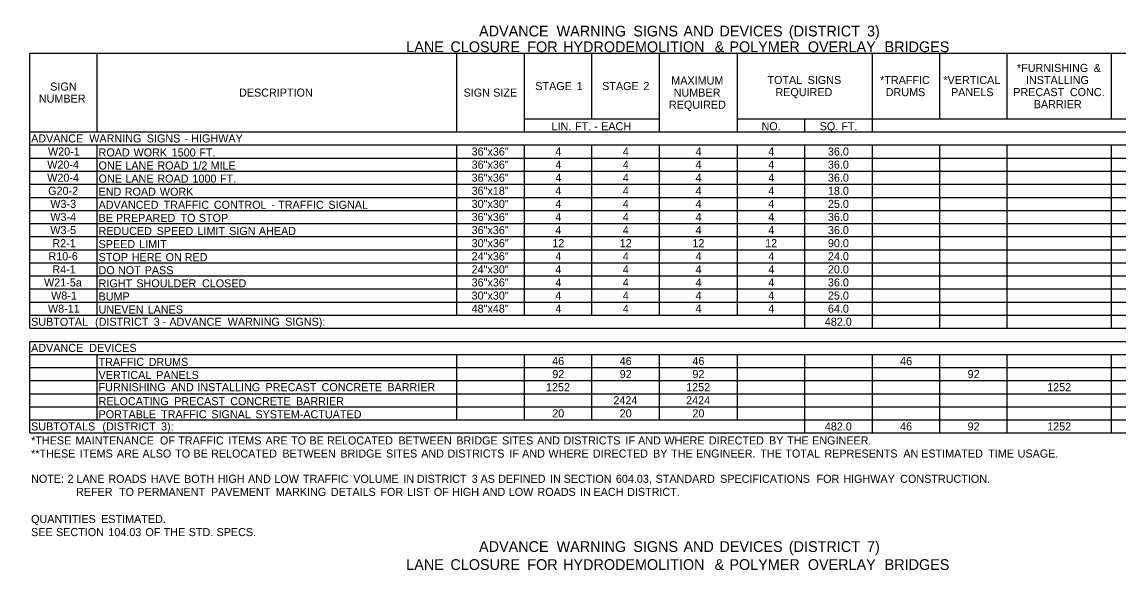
# Model space of a CAD drawing. Extents: x 544478 to 1930787, y -1948294 to 596640.
# Drawn here: x 544478 to 545294, y -1946531 to -1946122 of the extents above; entities that cross this region are included whole.
import ezdxf

# ---------------------------------------------------------------- set-up
doc = ezdxf.new("R2010")
doc.units = 0
doc.layers.add('Default', color=7, linetype='Continuous')

msp = doc.modelspace()

# ---------------------------------------------------------------- linework, layer by layer
at = {"layer": 'Default'}
for p, q in [((544478.43, -1946122.37), (544478.43, -1946122.37)), ((544484.28, -1946145.77), (545456.84, -1946145.77)), ((544484.28, -1946350.52), (544484.28, -1946145.77)), ((544484.28, -1946350.52), (544484.28, -1946145.77)), ((544534.49, -1946204.27), (544534.49, -1946145.77)), ((544802.13, -1946204.27), (544802.13, -1946145.77)), ((544852.34, -1946204.27), (544852.34, -1946145.77)), ((544902.55, -1946194.52), (544902.55, -1946145.77)), ((544952.76, -1946204.27), (544952.76, -1946145.77)), ((545010.78, -1946204.27), (545010.78, -1946145.77)), ((545111.2, -1946204.27), (545111.2, -1946145.77)), ((545161.41, -1946194.52), (545161.41, -1946145.77)), ((545211.63, -1946194.52), (545211.63, -1946145.77)), ((545289.14, -1946194.52), (545289.14, -1946145.77)), ((544852.34, -1946194.52), (544952.76, -1946194.52)), ((544952.76, -1946204.27), (544952.76, -1946194.52)), ((545010.78, -1946194.52), (545456.84, -1946194.52)), ((545060.99, -1946204.27), (545060.99, -1946194.52)), ((545111.2, -1946204.27), (545111.2, -1946194.52)), ((544484.28, -1946204.27), (545456.84, -1946204.27)), ((544952.76, -1946204.27), (545456.84, -1946204.27)), ((544484.28, -1946214.02), (545456.84, -1946214.02)), ((544534.49, -1946340.77), (544534.49, -1946214.02)), ((544534.49, -1946340.77), (544534.49, -1946214.02)), ((544802.13, -1946340.77), (544802.13, -1946214.02)), ((544802.13, -1946340.77), (544802.13, -1946214.02)), ((544852.34, -1946340.77), (544852.34, -1946214.02)), ((544852.34, -1946340.77), (544852.34, -1946214.02)), ((544902.55, -1946292.02), (544902.55, -1946214.02)), ((544902.55, -1946340.77), (544902.55, -1946214.02)), ((544952.76, -1946340.77), (544952.76, -1946214.02)), ((544952.76, -1946340.77), (544952.76, -1946214.02)), ((545010.78, -1946340.77), (545010.78, -1946214.02)), ((545060.99, -1946340.77), (545060.99, -1946214.02)), ((545060.99, -1946350.52), (545060.99, -1946214.02)), ((545111.2, -1946350.52), (545111.2, -1946214.02)), ((545111.2, -1946350.52), (545111.2, -1946214.02)), ((545161.41, -1946350.52), (545161.41, -1946214.02)), ((545161.41, -1946350.52), (545161.41, -1946214.02)), ((545211.63, -1946350.52), (545211.63, -1946214.02)), ((545211.63, -1946350.52), (545211.63, -1946214.02)), ((545289.14, -1946350.52), (545289.14, -1946214.02)), ((545289.14, -1946350.52), (545289.14, -1946214.02)), ((544484.28, -1946223.77), (545456.84, -1946223.77)), ((544484.28, -1946233.52), (545456.84, -1946233.52)), ((544484.28, -1946243.27), (545456.84, -1946243.27)), ((544484.28, -1946253.02), (545456.84, -1946253.02)), ((544484.28, -1946262.77), (545456.84, -1946262.77)), ((544484.28, -1946272.52), (545456.84, -1946272.52)), ((544484.28, -1946282.27), (545456.84, -1946282.27)), ((544484.28, -1946292.02), (545456.84, -1946292.02)), ((544484.28, -1946301.77), (545456.84, -1946301.77)), ((544902.55, -1946340.77), (544902.55, -1946301.77)), ((544484.28, -1946311.52), (545456.84, -1946311.52)), ((544484.28, -1946321.27), (545456.84, -1946321.27)), ((544484.28, -1946331.02), (545456.84, -1946331.02)), ((544484.28, -1946340.77), (545456.84, -1946340.77)), ((544484.28, -1946340.77), (545060.99, -1946340.77)), ((544484.28, -1946350.52), (545456.84, -1946350.52)), ((544484.28, -1946360.27), (545456.84, -1946360.27)), ((544484.28, -1946428.52), (544484.28, -1946360.27)), ((544484.28, -1946428.52), (544484.28, -1946360.27)), ((544534.49, -1946360.27), (545456.84, -1946360.27)), ((544484.28, -1946370.02), (545456.84, -1946370.02)), ((544534.49, -1946389.52), (544534.49, -1946370.02)), ((544534.49, -1946418.77), (544534.49, -1946370.02)), ((544802.13, -1946418.77), (544802.13, -1946370.02)), ((544802.13, -1946418.77), (544802.13, -1946370.02)), ((544852.34, -1946418.77), (544852.34, -1946370.02)), ((544852.34, -1946418.77), (544852.34, -1946370.02)), ((544902.55, -1946418.77), (544902.55, -1946370.02)), ((544902.55, -1946418.77), (544902.55, -1946370.02)), ((544952.76, -1946418.77), (544952.76, -1946370.02)), ((544952.76, -1946418.77), (544952.76, -1946370.02)), ((545010.78, -1946418.77), (545010.78, -1946370.02)), ((545060.99, -1946418.77), (545060.99, -1946370.02)), ((545060.99, -1946428.52), (545060.99, -1946370.02)), ((545111.2, -1946428.52), (545111.2, -1946370.02)), ((545111.2, -1946428.52), (545111.2, -1946370.02)), ((545161.41, -1946370.02), (545211.63, -1946370.02)), ((545161.41, -1946428.52), (545161.41, -1946370.02)), ((545161.41, -1946428.52), (545161.41, -1946370.02)), ((545211.63, -1946428.52), (545211.63, -1946370.02)), ((545289.14, -1946428.52), (545289.14, -1946370.02)), ((545289.14, -1946428.52), (545289.14, -1946370.02)), ((544484.28, -1946379.77), (545456.84, -1946379.77)), ((545211.63, -1946428.52), (545211.63, -1946379.77)), ((544484.28, -1946389.52), (545456.84, -1946389.52)), ((544484.28, -1946399.27), (544534.49, -1946399.27)), ((544484.28, -1946399.27), (544952.76, -1946399.27)), ((544534.49, -1946418.77), (544534.49, -1946399.27)), ((544802.13, -1946399.27), (544952.76, -1946399.27)), ((544952.76, -1946399.27), (545289.14, -1946399.27)), ((545010.78, -1946399.27), (545211.63, -1946399.27)), ((545211.63, -1946399.27), (545456.84, -1946399.27)), ((544484.28, -1946409.02), (545456.84, -1946409.02)), ((544484.28, -1946418.77), (545456.84, -1946418.77)), ((544484.28, -1946428.52), (545456.84, -1946428.52))]:
    msp.add_line(p, q, dxfattribs=at)

# ---------------------------------------------------------------- texts
for s, height, p in [('ADVANCE', 8, (544818.57, -1946133.2)), (' WARNING', 8, (544873.29, -1946133.2)), (' SIGNS', 8, (544930.36, -1946133.2)), (' AND', 8, (544967.7, -1946133.2)), (' DEVICES', 8, (544994.47, -1946133.2)), (' (DISTRICT', 8, (545046.1, -1946133.2)), (' 3)', 8, (545104.24, -1946133.2)), ('LANE', 8, (544764.4, -1946144.9)), (' CLOSURE', 8, (544794.28, -1946144.9)), (' FOR', 8, (544851.49, -1946144.9)), (' HYDRODEMOLITION', 8, (544878.13, -1946144.9)), (' &', 8, (544990.88, -1946144.9)), (' POLYMER', 8, (545001.88, -1946144.9)), (' OVERLAY', 8, (545060.21, -1946144.9)), (' BRIDGES', 8, (545117.37, -1946144.9)), ('*FURNISHING', 6, (545218.8, -1946159.65)), (' &', 6, (545273.72, -1946159.65)), ('SIGN', 6, (544499.47, -1946173.52)), ('STAGE', 6, (544860.4, -1946173.15)), (' 1', 6, (544888.86, -1946173.15)), ('STAGE', 6, (544910.14, -1946173.15)), (' 2', 6, (544938.61, -1946173.15)), ('MAXIMUM', 6, (544961.58, -1946169.02)), ('TOTAL', 6, (545033.14, -1946168.65)), (' SIGNS', 6, (545060.83, -1946168.65)), ('*TRAFFIC', 6, (545116.96, -1946168.65)), ('*VERTICAL', 6, (545164.05, -1946168.65)), ('INSTALLING', 6, (545225.49, -1946168.65)), ('NUMBER', 6, (544491, -1946182.52)), ('DESCRIPTION', 6, (544639.99, -1946178.02)), ('SIGN', 6, (544807.05, -1946178.02)), (' SIZE', 6, (544826.87, -1946178.02)), ('NUMBER', 6, (544963.39, -1946178.02)), ('REQUIRED', 6, (545039.07, -1946177.65)), ('DRUMS', 6, (545121.14, -1946177.65)), ('PANELS', 6, (545169.72, -1946177.65)), ('PRECAST', 6, (545216.05, -1946177.65)), (' CONC.', 6, (545255.94, -1946177.65)), ('REQUIRED', 6, (544959.85, -1946187.02)), ('BARRIER', 6, (545231.3, -1946186.65)), ('LIN.', 6, (544872.51, -1946203.07)), (' FT.', 6, (544887.77, -1946203.07)), (' -', 6, (544902.09, -1946203.07)), (' EACH', 6, (544907.15, -1946203.07)), ('NO.', 6, (545028.72, -1946203.07)), ('SQ.', 6, (545072, -1946203.07)), (' FT.', 6, (545085.87, -1946203.07)), ('ADVANCE', 6, (544485.25, -1946212.15)), (' WARNING', 6, (544526.29, -1946212.15)), (' SIGNS', 6, (544569.09, -1946212.15)), (' HIGHWAY', 6, (544602.16, -1946212.15)), ('W20-1', 6, (544497.81, -1946221.9)), ('ROAD', 6, (544535.46, -1946222.57)), (' WORK', 6, (544559.24, -1946222.57)), (' 1500', 6, (544587.63, -1946222.57)), (' -', 6, (544597.1, -1946212.15)), (' FT.', 6, (544608.19, -1946222.57)), ('36"x36"', 6, (544813.03, -1946221.9)), ('4', 6, (544875.32, -1946221.9)), ('4', 6, (544925.53, -1946221.9)), ('4', 6, (544979.64, -1946221.9)), ('4', 6, (545033.75, -1946221.9)), ('36.0', 6, (545078.14, -1946221.9)), ('W20-4', 6, (544497.24, -1946231.65)), ('36"x36"', 6, (544813.03, -1946231.65)), ('36.0', 6, (545078.14, -1946231.65)), ('ONE', 6, (544535.46, -1946232.32)), (' LANE', 6, (544553.18, -1946232.32)), (' ROAD', 6, (544576.96, -1946232.32)), (' 1/2', 6, (544603.07, -1946232.32)), (' MILE', 6, (544616.6, -1946232.32)), ('4', 6, (544875.32, -1946231.65)), ('4', 6, (544925.53, -1946231.65)), ('4', 6, (544979.64, -1946231.65)), ('4', 6, (545033.75, -1946231.65)), ('W20-4', 6, (544497.24, -1946241.4)), ('ONE', 6, (544535.46, -1946242.07)), (' LANE', 6, (544553.18, -1946242.07)), (' ROAD', 6, (544576.96, -1946242.07)), (' 1000', 6, (544603.07, -1946242.07)), (' FT.', 6, (544623.63, -1946242.07)), ('36"x36"', 6, (544813.03, -1946241.4)), ('4', 6, (544875.32, -1946241.4)), ('4', 6, (544925.53, -1946241.4)), ('4', 6, (544979.64, -1946241.4)), ('4', 6, (545033.75, -1946241.4)), ('36.0', 6, (545078.14, -1946241.4)), ('G20-2', 6, (544497.96, -1946251.15)), ('END', 6, (544535.46, -1946251.82)), (' ROAD', 6, (544552.72, -1946251.82)), (' WORK', 6, (544578.82, -1946251.82)), ('36"x18"', 6, (544813.03, -1946251.15)), ('4', 6, (544875.32, -1946251.15)), ('4', 6, (544925.53, -1946251.15)), ('4', 6, (544979.64, -1946251.15)), ('4', 6, (545033.75, -1946251.15)), ('18.0', 6, (545078.14, -1946251.15)), ('W3-3', 6, (544499.56, -1946260.9)), ('ADVANCED', 6, (544535.46, -1946261.57)), (' TRAFFIC', 6, (544581.61, -1946261.57)), (' CONTROL', 6, (544619, -1946261.57)), (' TRAFFIC', 6, (544666.87, -1946261.57)), (' SIGNAL', 6, (544704.26, -1946261.57)), ('30"x30"', 6, (544813.03, -1946260.9)), ('4', 6, (544875.32, -1946260.9)), ('4', 6, (544925.53, -1946260.9)), ('4', 6, (544979.64, -1946260.9)), ('4', 6, (545033.75, -1946260.9)), ('25.0', 6, (545078.14, -1946260.9)), ('W3-4', 6, (544499.57, -1946270.65)), ('BE', 6, (544535.46, -1946271.32)), (' PREPARED', 6, (544546.2, -1946271.32)), (' TO', 6, (544594.21, -1946271.32)), (' STOP', 6, (544607.81, -1946271.32)), (' -', 6, (544662.02, -1946261.57)), ('36"x36"', 6, (544813.03, -1946270.65)), ('4', 6, (544875.32, -1946270.65)), ('4', 6, (544925.53, -1946270.65)), ('4', 6, (544979.64, -1946270.65)), ('4', 6, (545033.75, -1946270.65)), ('36.0', 6, (545078.14, -1946270.65)), ('W3-5', 6, (544499.54, -1946280.4)), ('36"x36"', 6, (544813.03, -1946280.4)), ('4', 6, (544875.32, -1946280.4)), ('4', 6, (544925.53, -1946280.4)), ('4', 6, (544979.64, -1946280.4)), ('4', 6, (545033.75, -1946280.4)), ('36.0', 6, (545078.14, -1946280.4)), ('REDUCED', 6, (544535.46, -1946281.07)), (' SPEED', 6, (544576.47, -1946281.07)), (' LIMIT', 6, (544606.78, -1946281.07)), (' SIGN', 6, (544630.36, -1946281.07)), (' AHEAD', 6, (544652.5, -1946281.07)), ('R2-1', 6, (544501.07, -1946290.15)), ('SPEED', 6, (544535.46, -1946290.82)), (' LIMIT', 6, (544563.44, -1946290.82)), ('30"x36"', 6, (544813.03, -1946290.15)), ('12', 6, (544873.01, -1946290.15)), ('12', 6, (544923.22, -1946290.15)), ('12', 6, (544977.33, -1946290.15)), ('12', 6, (545031.44, -1946290.15)), ('90.0', 6, (545078.14, -1946290.15)), ('R10-6', 6, (544498.16, -1946299.9)), ('STOP', 6, (544535.46, -1946300.57)), (' HERE', 6, (544557.93, -1946300.57)), (' ON', 6, (544583.1, -1946300.57)), (' RED', 6, (544597.32, -1946300.57)), ('24"x36"', 6, (544813.03, -1946299.9)), ('4', 6, (544875.32, -1946299.9)), ('4', 6, (544925.53, -1946299.9)), ('4', 6, (544979.64, -1946299.9)), ('4', 6, (545033.75, -1946299.9)), ('24.0', 6, (545078.14, -1946299.9)), ('R4-1', 6, (544501.07, -1946309.65)), ('DO', 6, (544535.46, -1946310.32)), (' NOT', 6, (544547.66, -1946310.32)), (' PASS', 6, (544567.52, -1946310.32)), ('24"x30"', 6, (544813.03, -1946309.65)), ('4', 6, (544875.32, -1946309.65)), ('4', 6, (544925.53, -1946309.65)), ('4', 6, (544979.64, -1946309.65)), ('4', 6, (545033.75, -1946309.65)), ('20.0', 6, (545078.14, -1946309.65)), ('W21-5a', 6, (544494.89, -1946319.4)), ('RIGHT', 6, (544535.46, -1946320.07)), (' SHOULDER', 6, (544561.37, -1946320.07)), (' CLOSED', 6, (544610.17, -1946320.07)), ('36"x36"', 6, (544813.03, -1946319.4)), ('4', 6, (544875.32, -1946319.4)), ('4', 6, (544925.53, -1946319.4)), ('4', 6, (544979.64, -1946319.4)), ('4', 6, (545033.75, -1946319.4)), ('36.0', 6, (545078.14, -1946319.4)), ('W8-1', 6, (544500.14, -1946329.15)), ('30"x30"', 6, (544813.03, -1946329.15)), ('4', 6, (544875.32, -1946329.15)), ('4', 6, (544925.53, -1946329.15)), ('4', 6, (544979.64, -1946329.15)), ('4', 6, (545033.75, -1946329.15)), ('25.0', 6, (545078.14, -1946329.15)), ('BUMP', 6, (544535.46, -1946329.82)), ('W8-11', 6, (544497.81, -1946338.9)), ('UNEVEN', 6, (544535.46, -1946339.57)), (' LANES', 6, (544569.72, -1946339.57)), ('48"x48"', 6, (544813.03, -1946338.9)), ('4', 6, (544875.32, -1946338.9)), ('4', 6, (544925.53, -1946338.9)), ('4', 6, (544979.64, -1946338.9)), ('4', 6, (545033.75, -1946338.9)), ('64.0', 6, (545078.14, -1946338.9)), ('SUBTOTAL', 6, (544485.25, -1946348.65)), (' (DISTRICT', 6, (544530.64, -1946348.65)), (' 3', 6, (544574.24, -1946348.65)), (' -', 6, (544580.87, -1946348.65)), (' ADVANCE', 6, (544585.93, -1946348.65)), (' WARNING', 6, (544629.3, -1946348.65)), (' SIGNS):', 6, (544672.1, -1946348.65)), ('482.0', 6, (545075.82, -1946348.65)), ('ADVANCE', 6, (544485.25, -1946368.15)), (' DEVICES', 6, (544526.29, -1946368.15)), ('46', 6, (544872.97, -1946377.9)), ('46', 6, (544923.19, -1946377.9)), ('46', 6, (544977.3, -1946377.9)), ('46', 6, (545131.84, -1946377.9)), ('TRAFFIC', 6, (544535.46, -1946378.57)), (' DRUMS', 6, (544570.53, -1946378.57)), ('VERTICAL', 6, (544535.46, -1946388.32)), (' PANELS', 6, (544576.16, -1946388.32)), ('92', 6, (544873.01, -1946387.65)), ('92', 6, (544923.22, -1946387.65)), ('92', 6, (544977.33, -1946387.65)), ('92', 6, (545182.08, -1946387.65)), ('FURNISHING', 6, (544535.46, -1946397.4)), (' AND', 6, (544587.1, -1946397.4)), (' INSTALLING', 6, (544606.69, -1946397.4)), (' PRECAST', 6, (544657.4, -1946397.4)), (' CONCRETE', 6, (544699.16, -1946397.4)), (' BARRIER', 6, (544748.09, -1946397.4)), ('1252', 6, (544868.35, -1946397.4)), ('1252', 6, (544972.67, -1946397.4)), ('1252', 6, (545241.28, -1946397.4)), ('RELOCATING', 6, (544535.46, -1946407.82)), (' PRECAST', 6, (544589.44, -1946407.82)), (' CONCRETE', 6, (544631.2, -1946407.82)), (' BARRIER', 6, (544680.13, -1946407.82)), ('2424', 6, (544918.54, -1946407.15)), ('2424', 6, (544972.65, -1946407.15)), ('PORTABLE', 6, (544535.46, -1946417.57)), (' TRAFFIC', 6, (544579.74, -1946417.57)), (' SIGNAL', 6, (544617.13, -1946417.57)), (' SYSTEM-ACTUATED', 6, (544649.92, -1946417.57)), ('20', 6, (544872.99, -1946416.9)), ('20', 6, (544923.2, -1946416.9)), ('20', 6, (544977.31, -1946416.9)), ('SUBTOTALS', 6, (544485.25, -1946426.65)), (' (DISTRICT', 6, (544536.08, -1946426.65)), (' 3):', 6, (544579.68, -1946426.65)), ('482.0', 6, (545075.82, -1946426.65)), ('46', 6, (545131.79, -1946426.65)), ('92', 6, (545182.07, -1946426.65)), ('1252', 6, (545241.27, -1946426.65)), ('*THESE', 6, (544485.25, -1946437.07)), (' MAINTENANCE', 6, (544516.02, -1946437.07)), (' OF', 6, (544578.92, -1946437.07)), (' TRAFFIC', 6, (544592.51, -1946437.07)), (' ITEMS', 6, (544629.9, -1946437.07)), (' ARE', 6, (544657.41, -1946437.07)), (' TO', 6, (544676.53, -1946437.07)), (' BE', 6, (544690.12, -1946437.07)), (' RELOCATED', 6, (544703.19, -1946437.07)), (' BETWEEN', 6, (544756.32, -1946437.07)), (' BRIDGE', 6, (544799.42, -1946437.07)), (' SITES', 6, (544833.44, -1946437.07)), (' AND', 6, (544859.56, -1946437.07)), (' DISTRICTS', 6, (544879.14, -1946437.07)), (' IF', 6, (544925.28, -1946437.07)), (' AND', 6, (544934.67, -1946437.07)), (' WHERE', 6, (544954.26, -1946437.07)), (' DIRECTED', 6, (544987.34, -1946437.07)), (' BY', 6, (545032.08, -1946437.07)), (' THE', 6, (545045.53, -1946437.07)), (' ENGINEER.', 6, (545064.18, -1946437.07)), ('**THESE', 6, (544485.25, -1946446.82)), (' ITEMS', 6, (544519.28, -1946446.82)), (' ARE', 6, (544546.79, -1946446.82)), (' ALSO', 6, (544565.91, -1946446.82)), (' TO', 6, (544590.23, -1946446.82)), (' BE', 6, (544603.82, -1946446.82)), (' RELOCATED', 6, (544616.89, -1946446.82)), (' BETWEEN', 6, (544670.02, -1946446.82)), (' BRIDGE', 6, (544713.12, -1946446.82)), (' SITES', 6, (544747.14, -1946446.82)), (' AND', 6, (544773.26, -1946446.82)), (' DISTRICTS', 6, (544792.84, -1946446.82)), (' IF', 6, (544838.98, -1946446.82)), (' AND', 6, (544848.37, -1946446.82)), (' WHERE', 6, (544867.96, -1946446.82)), (' DIRECTED', 6, (544901.04, -1946446.82)), (' BY', 6, (544945.78, -1946446.82)), (' THE', 6, (544959.23, -1946446.82)), (' ENGINEER.', 6, (544977.88, -1946446.82)), (' THE', 6, (545025.59, -1946446.82)), (' TOTAL', 6, (545044.24, -1946446.82)), (' REPRESENTS', 6, (545073.29, -1946446.82)), (' AN', 6, (545132.02, -1946446.82)), (' ESTIMATED', 6, (545145.31, -1946446.82)), (' TIME', 6, (545195.18, -1946446.82)), (' USAGE.', 6, (545217.08, -1946446.82)), ('NOTE:', 6, (544485.25, -1946465.65)), (' 2', 6, (544510.14, -1946465.65)), (' LANE', 6, (544516.68, -1946465.65)), (' ROADS', 6, (544540.46, -1946465.65)), (' HAVE', 6, (544572.17, -1946465.65)), (' BOTH', 6, (544596.88, -1946465.65)), (' HIGH', 6, (544621.82, -1946465.65)), (' AND', 6, (544644.43, -1946465.65)), (' LOW', 6, (544664.02, -1946465.65)), (' TRAFFIC', 6, (544685.34, -1946465.65)), (' VOLUME', 6, (544722.73, -1946465.65)), (' IN', 6, (544760.02, -1946465.65)), (' DISTRICT', 6, (544770.04, -1946465.65)), (' 3', 6, (544810.86, -1946465.65)), (' AS', 6, (544817.46, -1946465.65)), (' DEFINED', 6, (544830.54, -1946465.65)), (' IN', 6, (544869.22, -1946465.65)), (' SECTION', 6, (544879.24, -1946465.65)), (' 604.03,', 6, (544918.15, -1946465.65)), (' STANDARD', 6, (544947.69, -1946465.65)), (' SPECIFICATIONS', 6, (544995.69, -1946465.65)), (' FOR', 6, (545067.46, -1946465.65)), (' HIGHWAY', 6, (545087.37, -1946465.65)), (' CONSTRUCTION.', 6, (545129.69, -1946465.65)), ('               REFER', 6, (544485.25, -1946475.4)), (' TO', 6, (544548.47, -1946475.4)), (' PERMANENT', 6, (544562.07, -1946475.4)), (' PAVEMENT', 6, (544616.87, -1946475.4)), (' MARKING', 6, (544665.15, -1946475.4)), (' DETAILS', 6, (544706.08, -1946475.4)), (' FOR', 6, (544742.91, -1946475.4)), (' LIST', 6, (544762.82, -1946475.4)), (' OF', 6, (544782.68, -1946475.4)), (' HIGH', 6, (544796.27, -1946475.4)), (' AND', 6, (544818.88, -1946475.4)), (' LOW', 6, (544838.46, -1946475.4)), (' ROADS', 6, (544859.79, -1946475.4)), (' IN', 6, (544891.49, -1946475.4)), (' EACH', 6, (544901.52, -1946475.4)), (' DISTRICT.', 6, (544926.47, -1946475.4)), ('QUANTITIES', 6, (544485.25, -1946495.57)), (' ESTIMATED.', 6, (544535.12, -1946495.57)), ('SEE', 6, (544485.25, -1946505.32)), (' SECTION', 6, (544501.58, -1946505.32)), (' 104.03', 6, (544540.49, -1946505.32)), (' OF', 6, (544568.07, -1946505.32)), (' THE', 6, (544581.65, -1946505.32)), (' STD.', 6, (544600.3, -1946505.32)), (' SPECS.', 6, (544621, -1946505.32)), ('ADVANCE', 8, (544818.57, -1946517.1)), (' WARNING', 8, (544873.29, -1946517.1)), (' SIGNS', 8, (544930.36, -1946517.1)), (' AND', 8, (544967.7, -1946517.1)), (' DEVICES', 8, (544994.47, -1946517.1)), (' (DISTRICT', 8, (545046.1, -1946517.1)), (' 7)', 8, (545104.24, -1946517.1)), ('LANE', 8, (544764.4, -1946530.51)), (' CLOSURE', 8, (544794.28, -1946530.51)), (' FOR', 8, (544851.49, -1946530.51)), (' HYDRODEMOLITION', 8, (544878.13, -1946530.51)), (' &', 8, (544990.88, -1946530.51)), (' POLYMER', 8, (545001.88, -1946530.51)), (' OVERLAY', 8, (545060.21, -1946530.51)), (' BRIDGES', 8, (545117.37, -1946530.51))]:
    msp.add_text(s, height=height, dxfattribs=at).set_placement(p)

doc.saveas('drawing.dxf')
